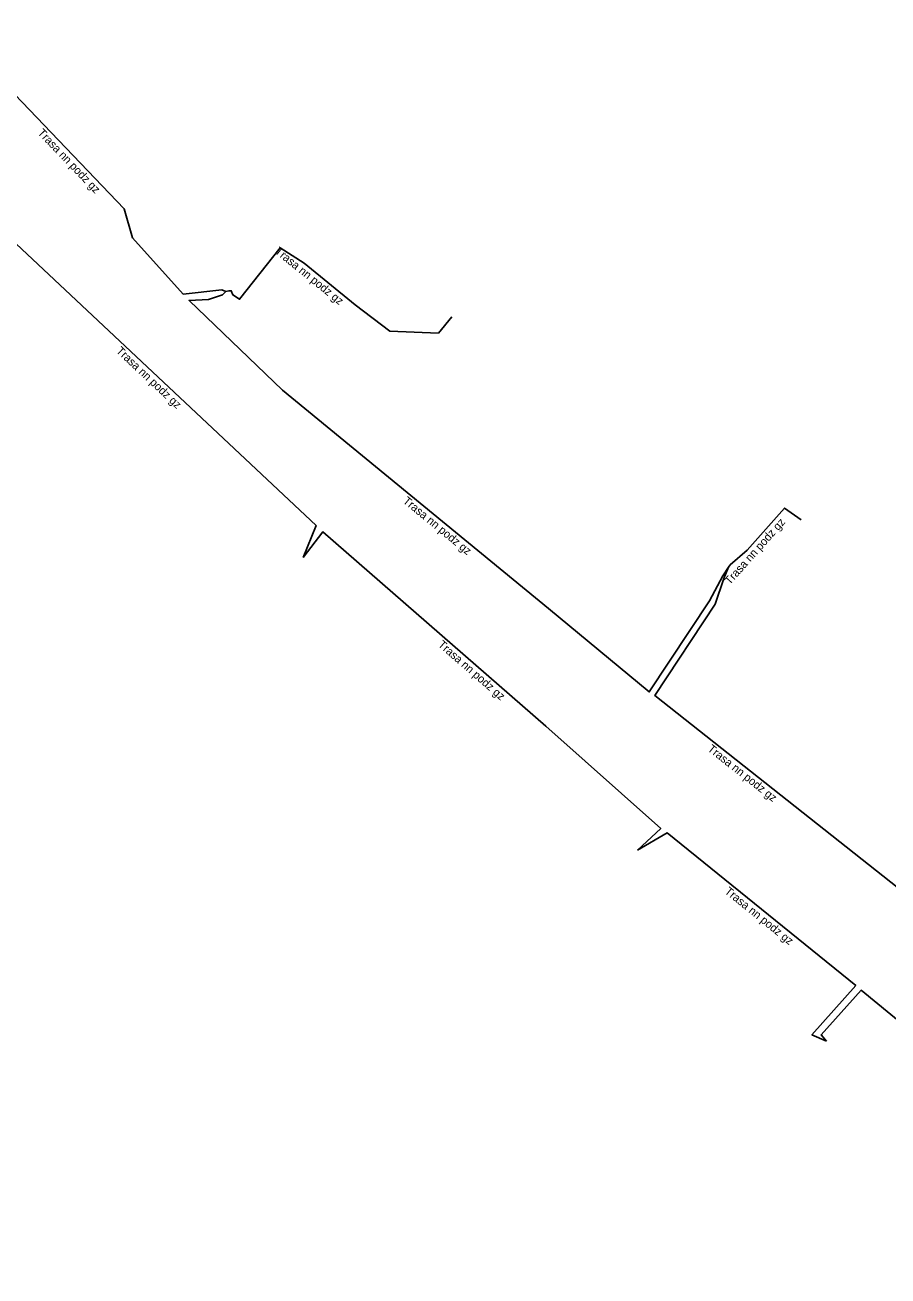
# Model space of a CAD drawing. Extents: x -484846 to -484244, y -1128177 to -1127608.
# Drawn here: x -484479.3 to -484426.4, y -1128086.6 to -1128009.8 of the extents above; entities that cross this region are included whole.
import ezdxf

# ---------------------------------------------------------------- set-up
doc = ezdxf.new("R2010")
doc.units = 0
doc.layers.add('Popiskový text - Ostatní atributy Trasy', color=7, linetype='Continuous')
doc.layers.add('Spojnice NN', color=7, linetype='Continuous')

msp = doc.modelspace()

# ---------------------------------------------------------------- linework, layer by layer
at = {"layer": 'Spojnice NN'}
for points in [[(-484482.47, -1128009.81), (-484483.126, -1128010.797), (-484473.27, -1128021.1), (-484472.75, -1128022.88), (-484469.654, -1128026.326), (-484467.278, -1128026.071), (-484467.024, -1128026.17)], [(-484481.071, -1128024.348), (-484480.55, -1128023.907), (-484479.88, -1128023.25), (-484461.492, -1128040.542), (-484462.273, -1128042.494)], [(-484467.024, -1128026.17), (-484466.834, -1128026.127), (-484466.696, -1128026.127), (-484466.604, -1128026.385), (-484466.18, -1128026.65), (-484463.7, -1128023.48), (-484462.23, -1128024.43), (-484459.09, -1128026.98), (-484456.97, -1128028.61), (-484453.99, -1128028.72), (-484453.16, -1128027.72)], [(-484467.024, -1128026.17), (-484467.224, -1128026.373), (-484468.081, -1128026.669), (-484469.28, -1128026.713), (-484463.55, -1128032.23), (-484447.23, -1128045.63), (-484441.048, -1128050.751), (-484437.356, -1128045.162), (-484436.533, -1128043.628), (-484436.189, -1128043.101)], [(-484436.189, -1128043.101), (-484436.08, -1128042.954), (-484435.05, -1128042.046), (-484432.749, -1128039.464), (-484431.732, -1128040.179)], [(-484462.273, -1128042.494), (-484461.074, -1128040.921), (-484447.4, -1128052.85), (-484440.35, -1128059.13), (-484441.766, -1128060.477)], [(-484436.189, -1128043.101), (-484436.483, -1128043.799), (-484437.004, -1128045.358), (-484440.712, -1128050.969), (-484424.85, -1128063.514), (-484422.078, -1128059.675), (-484421.58, -1128060.7)], [(-484441.766, -1128060.477), (-484439.949, -1128059.41), (-484428.38, -1128068.786), (-484431.073, -1128071.802), (-484430.181, -1128072.191)], [(-484430.181, -1128072.191), (-484430.51, -1128071.81), (-484428.05, -1128069.07), (-484407.69, -1128085.784), (-484407.884, -1128086.329), (-484408.15, -1128086.611)]]:
    msp.add_lwpolyline(points, dxfattribs=at)

# ---------------------------------------------------------------- texts
at = {"layer": 'Popiskový text - Ostatní atributy Trasy'}
for rotation, p in [(313.72975, (-484478.606, -1128016.462)), (320.91988, (-484464.063, -1128023.778)), (316.75943, (-484473.793, -1128029.867)), (320.61132, (-484456.203, -1128039.103)), (48.29354, (-484436.109, -1128044.211)), (318.89903, (-484454.049, -1128047.912)), (321.6601, (-484437.513, -1128054.328)), (320.97725, (-484436.468, -1128063.068))]:
    msp.add_text('Trasa nn podz gz', height=0.5, rotation=rotation, dxfattribs=at).set_placement(p)

doc.saveas('drawing.dxf')
